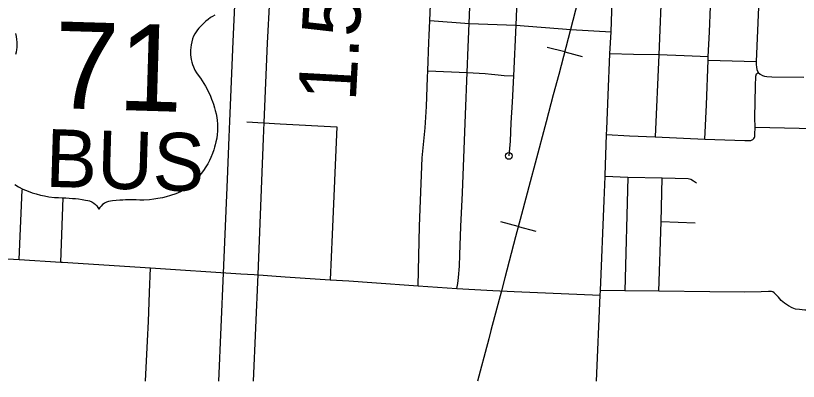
# Model space of a CAD drawing. Extents: x 653372 to 905732, y 627442 to 787275.
# Drawn here: x 684356 to 690080, y 728634 to 731305 of the extents above; entities that cross this region are included whole.
import ezdxf

# ---------------------------------------------------------------- set-up
doc = ezdxf.new("R2010")
doc.units = 0
for name, color, linetype in [('15', 7, 'Continuous'), ('22', 7, 'Continuous'), ('33', 7, 'Continuous'), ('40', 7, 'Continuous'), ('48', 7, 'Continuous')]:
    doc.layers.add(name, color=color, linetype=linetype)

msp = doc.modelspace()

# ---------------------------------------------------------------- linework, layer by layer
at = {"layer": '15'}
for points in [[(685842.9, 728633.5), (685876.9, 729423.6), (685904.5, 730107.4), (685916.8, 730417.3), (685921.7, 730535.2), (685946.3, 731115.9), (685961.9, 731435.1), (685969.1, 731565), (685989.7, 731762.3), (686004.9, 731901.4), (686009.6, 731957.1), (686016.8, 732095.5), (686043.1, 732736.1), (686043.8, 732747.6), (686071.2, 733397.3)], [(686321, 733387.1), (686293.5, 732734.4), (686292.8, 732723.2), (686266.6, 732083.9), (686259, 731940.2), (686253.8, 731877.4), (686238.3, 731735.7), (686218.4, 731545.2), (686211.6, 731422.1), (686196, 731104.4), (686171.4, 730524.8), (686166.6, 730407.1), (686154.2, 730097.4), (686126.7, 729413.2), (686093.1, 728633.5)]]:
    msp.add_lwpolyline(points, dxfattribs=at)
at = {"layer": '22'}
for points in [[(685811.5, 731308.9), (685796.5, 731299.7), (685782.2, 731290.3), (685763.2, 731276.3), (685748, 731264), (685734.5, 731252.1), (685720.7, 731238.9), (685706.5, 731224), (685696.3, 731212.5), (685686.2, 731200.2), (685675.9, 731186.8), (685665.9, 731172.6), (685656.6, 731155.8), (685649.2, 731135.2), (685643.5, 731114.7), (685639, 731092.7), (685636.3, 731072.3), (685635, 731052.5), (685635, 731033.9), (685635.7, 731019), (685637.7, 731000.7), (685640.5, 730983.5), (685644.7, 730964.8), (685649.5, 730948.4), (685656.1, 730929.9), (685666.6, 730905.9), (685677.6, 730887.1), (685691, 730870), (685707.3, 730847.7), (685720.5, 730828.2), (685732.7, 730808.8), (685743.9, 730789.7), (685753.3, 730772.7), (685761.5, 730756.7), (685770.7, 730737.7), (685780.5, 730715.6), (685789.3, 730694), (685795.3, 730677.9), (685802.3, 730657.3), (685810, 730632.1), (685816.1, 730611.2), (685821.7, 730588.4), (685826.7, 730561.9), (685829.8, 730538.5), (685831.9, 730514), (685832.7, 730487.3), (685832.1, 730462.3), (685830.2, 730437.9), (685826.3, 730409.3), (685821.1, 730382.2), (685816, 730361.8), (685810.7, 730343.9), (685804.2, 730323.6), (685795.5, 730298.4), (685783.1, 730268), (685772.6, 730245.6), (685760.5, 730222.6), (685747.3, 730200.1), (685730.2, 730174.3), (685712.6, 730150.7), (685695.7, 730130.1), (685676.5, 730109.2), (685651.9, 730085.1), (685631, 730066.9), (685609.6, 730050)], [(684355.4, 731174), (684359.9, 731153.2), (684363.1, 731131), (684364.5, 731110.5), (684364.6, 731090.6), (684363.6, 731072.1), (684361.9, 731057.2), (684358.9, 731039.1), (684355, 731022.1)], [(684351.1, 730071.4), (684376.7, 730053.6), (684408.9, 730037.9), (684446.8, 730022.1), (684477.8, 730011), (684505.7, 730002.3), (684537.3, 729994), (684566.9, 729987.6), (684598.9, 729982.2), (684639.3, 729977.6), (684670.2, 729975.5), (684696.7, 729974.9), (684722.4, 729973.8), (684748.2, 729972.3), (684772.6, 729970.3), (684793.8, 729968.2), (684814.8, 729965.8), (684841.6, 729962.2), (684867.8, 729958.2), (684883.4, 729955.5), (684896.4, 729952.6), (684912, 729945.6), (684920.8, 729940.3), (684928.5, 729934.9), (684939.1, 729925.8), (684949.1, 729915.1), (684957.2, 729904), (684964.4, 729891.3)], [(685609.6, 730050), (685587.4, 730034.2), (685560.8, 730018), (685527.6, 730004.3), (685488.9, 729990.8), (685457.3, 729981.5), (685429, 729974.6), (685396.9, 729968.2), (685366.9, 729963.6), (685334.7, 729960.2), (685294.1, 729957.9), (685263.1, 729957.7), (685236.6, 729958.7), (685210.9, 729959.2), (685185.1, 729959.2), (685160.6, 729958.7), (685139.3, 729957.9), (685118.2, 729956.7), (685091.3, 729954.7), (685064.9, 729952.3), (685049.1, 729950.5), (685035.9, 729948.4), (685020, 729942.3), (685010.8, 729937.6), (685002.8, 729932.6), (684991.8, 729924.3), (684981.1, 729914.1), (684972.4, 729903.6), (684964.4, 729891.3)]]:
    msp.add_lwpolyline(points, dxfattribs=at)
at = {"layer": '33'}
for points in [[(688106, 733442), (688100, 733264.9), (688084.9, 732925.1), (688068.5, 732585.4), (688060.6, 732413), (688052.9, 732246.1), (688042.2, 731959.8), (688035.1, 731779.3), (688028.3, 731599.9), (688013.6, 731235.3), (687995.7, 730866.5), (687986.1, 730672.2), (687978.5, 730521.9), (687972, 730389), (687962.6, 730280.8)], [(687300.7, 729330.5), (687308.9, 729766.6), (687329.1, 730265.1), (687351.5, 730485.7), (687359.9, 730641), (687367.1, 730854.3), (687370, 730900.9), (687378.4, 731110.3), (687380.4, 731159.6), (687384.8, 731268.6), (687400.4, 731617.9), (687400.9, 731628.6), (687419.6, 732001.1), (687434.5, 732278.4), (687436.6, 732340.8), (687449.5, 732622), (687450.8, 732665.6), (687461.9, 732961.6)], [(687581.4, 729312.3), (687589.6, 729349), (687594.6, 729393), (687600.8, 729474.3), (687603.3, 729556.9), (687612, 729765.7), (687623.7, 730009.7), (687645.9, 730582.4), (687658.2, 730888.8), (687664.6, 731075.6), (687672.7, 731248.5), (687688.2, 731617.6), (687696.4, 731798.7), (687697.1, 731976.2)], [(689099, 731798.8), (689091.3, 731773.8), (689088.2, 731755.5), (689085.4, 731688.4), (689082.5, 731566.9), (689058.9, 731018.7), (689032.9, 730418.6)], [(689395.9, 730402.4), (689409.1, 730653.6), (689420.8, 730980.6), (689420.3, 730989.3), (689420.8, 731003.6), (689429.1, 731186.8), (689444.7, 731559.6), (689452.3, 731745.6)], [(688603.6, 728633.5), (688631.3, 729262.8), (688632.7, 729296.8), (688659, 729953.4), (688666.5, 730130.2), (688666.8, 730136.5), (688678, 730435.8), (688680.5, 730476.2), (688688.9, 730723.3), (688702.4, 731025.2), (688711.1, 731187.4), (688722.5, 731569.7)], [(689787.7, 731366.1), (689770.9, 730970.8), (689770.7, 730947.6), (689773.3, 730928.7), (689776.9, 730910.8), (689785.7, 730890.9), (689800.1, 730876.8), (689816.7, 730867.6), (689833.4, 730863.4), (689848.9, 730860.2), (689886.7, 730859.1), (690120.8, 730856.7)], [(687384.8, 731268.6), (687672.7, 731248.5), (688013.6, 731235.3), (688415.1, 731204.5), (688711.1, 731187.4)], [(689420.8, 731003.6), (689245.8, 731011.7), (689058.9, 731018.7), (688874.3, 731022.4), (688702.4, 731025.2)], [(689420.8, 730980.6), (689770.9, 730970.8)], [(687370, 730900.9), (687658.2, 730888.8), (687789.3, 730882.3), (687834.8, 730878.3), (687883.7, 730872.2), (687928.6, 730868.8), (687995.7, 730866.5)], [(688678, 730435.8), (688845.6, 730427.7), (689032.9, 730418.6), (689395.9, 730402.4), (689688.4, 730393.4), (689732.4, 730393.6), (689746.2, 730400.4), (689754.4, 730407.4), (689759.4, 730414.4), (689760.4, 730420.2), (689762.5, 730438.2), (689764.5, 730489.1), (689762.2, 730561.4), (689767.5, 730788.7), (689768.9, 730863.4), (689774.2, 730879.3), (689785.7, 730890.9)], [(686046.5, 730530), (686291.6, 730513.6), (686704.9, 730492.9)], [(686704.9, 730492.9), (686670.3, 729706.3), (686655.6, 729375.5)], [(690192.7, 730477.2), (689764.5, 730489.1)], [(689334.3, 730080.3), (689313.2, 730095.4), (689294.3, 730107.2), (689274.5, 730113.3), (689083, 730118.5), (688832.2, 730123.4), (688666.5, 730130.2)], [(688832.2, 730123.4), (688812.1, 729294.3)], [(689059.7, 729292.5), (689075.7, 729798.1), (689083, 730118.5)], [(684381.8, 729524.1), (684404.3, 730033.7)], [(684687.1, 729505.1), (684704.7, 729973.3)], [(689324.8, 729789.4), (689075.7, 729798.1)], [(680745.9, 729709.9), (681257.3, 729681.6), (681540.1, 729668.4), (681877.5, 729653.7), (681906.1, 729652.1), (682217.5, 729635.9), (682212.4, 729636.1), (682248.2, 729633.7), (682616.1, 729617.2), (682921.1, 729601.6), (683200.4, 729588.3), (683523.4, 729573.7), (684008.7, 729545.1), (684381.8, 729524.1), (684687.1, 729505.1), (684699.1, 729503.9), (685341.7, 729462.1), (686001.8, 729418.4)], [(685306.5, 728633.5), (685321.1, 728928.9), (685327.3, 729071.3), (685333.9, 729283.6), (685341.7, 729462.1)], [(686001.8, 729418.4), (686099.2, 729414), (686327.9, 729398.1), (686655.6, 729375.5), (686792.3, 729366.8), (686961.3, 729354.6), (687300.7, 729330.5), (687581.4, 729312.3), (687844.7, 729296.9), (688001.5, 729289.9), (688631.3, 729262.8)], [(690170.5, 729149.3), (690151.8, 729153), (690126.5, 729154.4), (690087.9, 729157.3), (690059.1, 729161.8), (690034.6, 729171), (690007.2, 729184.5), (689978.8, 729204.1), (689954.6, 729224.8), (689933.6, 729247.8), (689913.7, 729270.1), (689902.9, 729280.7), (689893.1, 729287.7), (689883.8, 729289.8), (689872.1, 729290.7), (689860.6, 729290.5), (689808.2, 729286.6), (689689.2, 729284.7), (689433.1, 729286.4), (689059.7, 729292.5), (688812.1, 729294.3), (688632.7, 729296.8)]]:
    msp.add_lwpolyline(points, dxfattribs=at)
msp.add_circle((687962.6, 730280.8), 25, dxfattribs=at)
at = {"layer": '40'}
for p, q in [((688371.1, 731039.8), (688243.5, 731073.4)), ((688371.1, 731039.8), (688498.8, 731006.3)), ((688032.1, 729764.1), (687904.6, 729798.1)), ((688032.1, 729764.1), (688159.7, 729730.1))]:
    msp.add_line(p, q, dxfattribs=at)
msp.add_lwpolyline([(688468, 731410.5), (688414.4, 731204.6), (688327.6, 730874.2), (688287.9, 730726.6), (688236, 730528.7), (688155, 730227.3), (688119.2, 730091.3), (688055.6, 729852.1), (688011.9, 729688.1), (687933.3, 729390.6), (687908.9, 729295), (687831.1, 729004.4), (687815.3, 728944.5), (687788.7, 728843.3), (687752.9, 728708.7), (687733, 728633.5)], dxfattribs=at)
msp.add_lwpolyline([(688468, 731410.5), (688414.4, 731204.6), (688327.6, 730874.2), (688287.9, 730726.6), (688236, 730528.7), (688155, 730227.3), (688119.2, 730091.3), (688055.6, 729852.1), (688011.9, 729688.1), (687933.3, 729390.6), (687908.9, 729295), (687831.1, 729004.4), (687815.3, 728944.5), (687788.7, 728843.3), (687752.9, 728708.7), (687733, 728633.5)], dxfattribs=at)

# ---------------------------------------------------------------- texts
at = {"layer": '22'}
for s, height, p in [('71', 633.6, (684628.5, 730630.3)), ('BUS', 422.4, (684570, 730055.4))]:
    msp.add_text(s, height=height, rotation=358.28, dxfattribs=at).set_placement(p)
at = {"layer": '48'}
msp.add_text('1.5', height=422.4, rotation=86.8484, dxfattribs=at).set_placement((686843.1, 730673.3))

doc.saveas('drawing.dxf')
